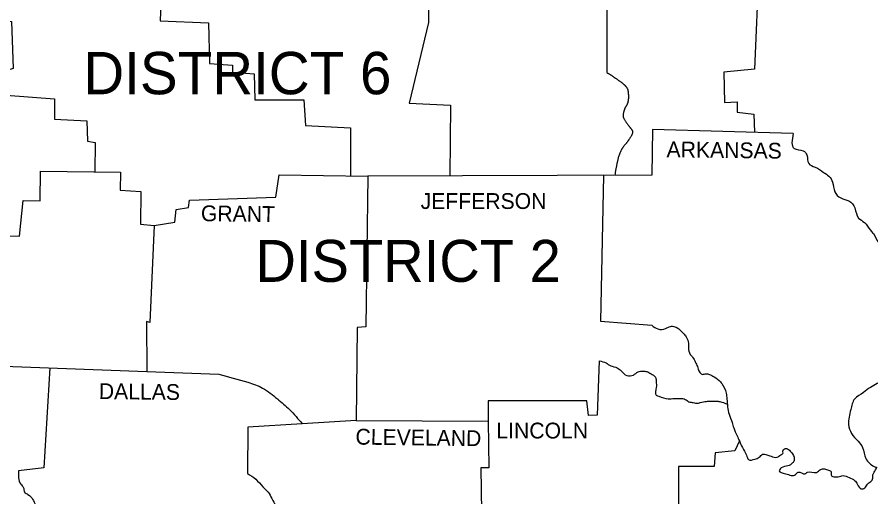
# Model space of a CAD drawing. Extents: x -0.3 to 2.65, y 0 to 1.9.
# Drawn here: x 1.1888 to 1.2937, y 0.6375 to 0.6965 of the extents above; entities that cross this region are included whole.
import ezdxf

# ---------------------------------------------------------------- set-up
doc = ezdxf.new("R2010")
doc.units = 0
doc.layers.add('Default', color=7, linetype='Continuous')

msp = doc.modelspace()

# ---------------------------------------------------------------- linework, layer by layer
at = {"layer": 'Default'}
for points in [[(1.25468, 0.71544), (1.25476, 0.70736), (1.26121, 0.70723), (1.26127, 0.68967)], [(1.23665, 0.7134), (1.2393, 0.71325), (1.23935, 0.69579), (1.23697, 0.68591), (1.24205, 0.68565), (1.24197, 0.67695)], [(1.27994, 0.70259), (1.27939, 0.69009), (1.27566, 0.6897), (1.27574, 0.68599), (1.27727, 0.68604), (1.27729, 0.68477), (1.27934, 0.68454), (1.27942, 0.68231)], [(1.2011, 0.70204), (1.20654, 0.70171), (1.20634, 0.696), (1.2123, 0.69577), (1.21243, 0.69079), (1.21523, 0.69056), (1.21523, 0.6897), (1.2179, 0.68949), (1.21798, 0.6863), (1.224, 0.6863), (1.22421, 0.68314), (1.22976, 0.68288), (1.22973, 0.67694)], [(1.18204, 0.69644), (1.18808, 0.69592), (1.18826, 0.69017), (1.18751, 0.68993), (1.18741, 0.68687), (1.19337, 0.68643), (1.19337, 0.68392), (1.19734, 0.68371), (1.19742, 0.68122), (1.19835, 0.68106), (1.19832, 0.67745)], [(1.28417, 0.68218), (1.26689, 0.68267), (1.26679, 0.67704), (1.23188, 0.67691)], [(1.16278, 0.66994), (1.18904, 0.66955), (1.18953, 0.67391), (1.19161, 0.67388), (1.19166, 0.67754), (1.20149, 0.67741), (1.20144, 0.6752), (1.20398, 0.67502), (1.20395, 0.67103), (1.20561, 0.67087)], [(1.20561, 0.67087), (1.20815, 0.67126), (1.20833, 0.67282), (1.20984, 0.67308), (1.20994, 0.67398), (1.22057, 0.67432), (1.22099, 0.67707), (1.23188, 0.67691)], [(1.26084, 0.67702), (1.26049, 0.6591), (1.26679, 0.6586)], [(1.23188, 0.67691), (1.23165, 0.6584), (1.23056, 0.65832), (1.23046, 0.64688)], [(1.20561, 0.67087), (1.20507, 0.65894), (1.20468, 0.65907), (1.2047, 0.65291)], [(1.15758, 0.65772), (1.15745, 0.66024), (1.1582, 0.66029), (1.15867, 0.6662), (1.16567, 0.66571), (1.16552, 0.66211), (1.17457, 0.66161), (1.17465, 0.65943), (1.18284, 0.65894), (1.18424, 0.65648), (1.18339, 0.65536), (1.1838, 0.65368), (1.2047, 0.65291)], [(1.26033, 0.65422), (1.26007, 0.64753), (1.25901, 0.6475), (1.2588, 0.64932), (1.24666, 0.64929), (1.24669, 0.6468)], [(1.19278, 0.65335), (1.19205, 0.64107), (1.18894, 0.64071)], [(1.2047, 0.65291), (1.21355, 0.65259)], [(1.23046, 0.64688), (1.22382, 0.64648)], [(1.23046, 0.64688), (1.24669, 0.6468)], [(1.24669, 0.6468), (1.24674, 0.64107), (1.24576, 0.64105), (1.24604, 0.62211)], [(1.22382, 0.64648), (1.21713, 0.64608), (1.21707, 0.64037)], [(1.27755, 0.64437), (1.27698, 0.64315), (1.27457, 0.64291), (1.27444, 0.64125), (1.27008, 0.64125), (1.27003, 0.62762)]]:
    msp.add_lwpolyline(points, dxfattribs=at)
msp.add_open_spline([(1.26127, 0.68967), (1.26136, 0.68961), (1.26146, 0.68955), (1.26156, 0.68948), (1.26165, 0.68942), (1.26175, 0.68936), (1.26184, 0.68929), (1.26203, 0.68916), (1.26222, 0.68903), (1.26241, 0.6889), (1.26251, 0.68883), (1.26261, 0.68876), (1.26271, 0.68869), (1.26281, 0.68863), (1.26291, 0.68856), (1.26301, 0.68849), (1.26311, 0.68842), (1.2632, 0.68834), (1.26329, 0.68826), (1.26334, 0.68822), (1.26339, 0.68818), (1.26344, 0.68813), (1.26346, 0.68811), (1.26348, 0.68809), (1.2635, 0.68806), (1.26353, 0.68804), (1.26355, 0.68801), (1.26357, 0.68799), (1.26365, 0.6879), (1.26371, 0.68781), (1.26376, 0.68771), (1.2638, 0.68761), (1.26384, 0.68751), (1.26386, 0.6874), (1.26387, 0.6873), (1.26389, 0.68719), (1.2639, 0.68708), (1.2639, 0.68703), (1.2639, 0.68698), (1.26391, 0.68693), (1.26391, 0.68687), (1.26391, 0.68682), (1.26391, 0.68677), (1.26391, 0.6867), (1.26391, 0.68663), (1.26391, 0.68655), (1.26391, 0.68648), (1.2639, 0.68641), (1.26389, 0.68634), (1.26389, 0.68627), (1.26387, 0.6862), (1.26386, 0.68612), (1.26385, 0.68605), (1.26383, 0.68598), (1.26381, 0.68591), (1.26379, 0.68585), (1.26376, 0.68578), (1.26373, 0.68572), (1.2637, 0.68566), (1.26366, 0.68561), (1.26363, 0.68555), (1.2636, 0.68549), (1.26356, 0.68543), (1.26353, 0.68537), (1.26349, 0.68531), (1.26347, 0.68525), (1.26344, 0.68519), (1.26343, 0.68514), (1.26341, 0.68509), (1.2634, 0.68505), (1.26338, 0.685), (1.26336, 0.68495), (1.26335, 0.6849), (1.26332, 0.6848), (1.2633, 0.6847), (1.26328, 0.6846), (1.26326, 0.6845), (1.26326, 0.6844), (1.26326, 0.6843), (1.26327, 0.68425), (1.26327, 0.6842), (1.26329, 0.68415), (1.2633, 0.68411), (1.26332, 0.68406), (1.26334, 0.68402), (1.26342, 0.68387), (1.26351, 0.68373), (1.2636, 0.6836), (1.26369, 0.68346), (1.26379, 0.68332), (1.26389, 0.68319), (1.26393, 0.68313), (1.26397, 0.68308), (1.26401, 0.68303), (1.26406, 0.68297), (1.2641, 0.68292), (1.26415, 0.68287), (1.26421, 0.68279), (1.26428, 0.68271), (1.26433, 0.68262), (1.26434, 0.68261), (1.26435, 0.6826), (1.26436, 0.68258), (1.26436, 0.68257), (1.26437, 0.68256), (1.26438, 0.68254), (1.26442, 0.68245), (1.26443, 0.68234), (1.26441, 0.68225), (1.26439, 0.68214), (1.26435, 0.68202), (1.26429, 0.68193), (1.26419, 0.68176), (1.26409, 0.6816), (1.26398, 0.68145), (1.26395, 0.6814), (1.26392, 0.68135), (1.26389, 0.6813), (1.26385, 0.68125), (1.26382, 0.68119), (1.26378, 0.68114), (1.26375, 0.68109), (1.26371, 0.68105), (1.26367, 0.681), (1.26359, 0.68091), (1.26351, 0.68081), (1.26344, 0.68072), (1.26336, 0.68063), (1.26329, 0.68053), (1.26321, 0.68044), (1.26318, 0.68039), (1.26315, 0.68034), (1.26312, 0.68029), (1.26308, 0.68024), (1.26306, 0.68018), (1.26303, 0.68013), (1.26293, 0.67993), (1.26284, 0.67973), (1.26277, 0.67952), (1.2627, 0.67931), (1.26264, 0.6791), (1.26259, 0.67888), (1.26255, 0.67873), (1.26252, 0.67858), (1.26249, 0.67842), (1.26246, 0.67827), (1.26243, 0.67811), (1.26239, 0.67796), (1.26236, 0.6778), (1.26234, 0.67765), (1.26231, 0.67749), (1.26228, 0.67734), (1.26226, 0.67718), (1.26223, 0.67703)], degree=3, dxfattribs=at)
for points in [[(1.28417, 0.68218), (1.2843, 0.68031), (1.2854, 0.68003), (1.28585, 0.67953), (1.28608, 0.67848), (1.28686, 0.67803), (1.28791, 0.67739), (1.28855, 0.67693), (1.289, 0.6762), (1.28928, 0.67501), (1.29001, 0.67424), (1.29101, 0.67387), (1.29174, 0.67301), (1.2922, 0.67177), (1.29293, 0.67123), (1.29366, 0.67027), (1.29402, 0.66986), (1.29466, 0.66876), (1.2953, 0.66821), (1.29576, 0.66789), (1.29649, 0.66767), (1.2974, 0.66707), (1.29799, 0.66616), (1.29799, 0.66547), (1.29777, 0.66443), (1.29758, 0.66333), (1.29749, 0.6621), (1.2974, 0.661), (1.29781, 0.66009), (1.29758, 0.65872), (1.29713, 0.65799), (1.29708, 0.65699), (1.29694, 0.65548), (1.29676, 0.65461), (1.29635, 0.6532), (1.2958, 0.65251)], [(1.28417, 0.68218), (1.2843, 0.68031), (1.2854, 0.68003), (1.28585, 0.67953), (1.28608, 0.67848), (1.28686, 0.67803), (1.28791, 0.67739), (1.28855, 0.67693), (1.289, 0.6762), (1.28928, 0.67501), (1.29001, 0.67424), (1.29101, 0.67387), (1.29174, 0.67301), (1.2922, 0.67177), (1.29293, 0.67123), (1.29366, 0.67027), (1.29402, 0.66986), (1.29466, 0.66876), (1.2953, 0.66821), (1.29576, 0.66789), (1.29649, 0.66767), (1.2974, 0.66707), (1.29799, 0.66616), (1.29799, 0.66547), (1.29777, 0.66443), (1.29758, 0.66333), (1.29749, 0.6621), (1.2974, 0.661), (1.29781, 0.66009), (1.29758, 0.65872), (1.29713, 0.65799), (1.29708, 0.65699), (1.29694, 0.65548), (1.29676, 0.65461), (1.29635, 0.6532), (1.29576, 0.65247)], [(1.26679, 0.6586), (1.26752, 0.65814), (1.26848, 0.65819), (1.26907, 0.65845), (1.26962, 0.65842), (1.27027, 0.65801), (1.27076, 0.65749), (1.27107, 0.65707), (1.27128, 0.6564), (1.27128, 0.65583), (1.27151, 0.655), (1.2718, 0.65466), (1.27213, 0.65409), (1.27239, 0.65352), (1.2725, 0.65318), (1.27301, 0.65256), (1.27348, 0.65264), (1.27387, 0.65256), (1.27444, 0.65225), (1.27524, 0.65163), (1.2754, 0.65142), (1.27592, 0.65025), (1.27602, 0.64953), (1.2761, 0.64857), (1.27628, 0.64766), (1.27667, 0.64665), (1.27685, 0.64597), (1.27727, 0.64501), (1.27755, 0.64437), (1.27792, 0.64356), (1.27843, 0.64263), (1.27869, 0.64208), (1.27947, 0.64214), (1.27999, 0.64237), (1.28041, 0.64273), (1.28092, 0.64268), (1.28144, 0.6425), (1.28219, 0.64237), (1.28264, 0.64265), (1.2829, 0.64284), (1.28292, 0.64323), (1.28334, 0.64346), (1.2838, 0.64312), (1.28427, 0.6424), (1.28427, 0.64195), (1.28409, 0.64167), (1.28352, 0.64131), (1.28269, 0.64105), (1.28245, 0.64071), (1.28323, 0.64035), (1.28445, 0.64024), (1.28479, 0.64055), (1.28562, 0.64032), (1.28593, 0.64053), (1.28702, 0.6405), (1.28754, 0.64087), (1.28852, 0.64079), (1.28883, 0.64058), (1.28883, 0.64019), (1.28969, 0.63998), (1.29029, 0.64011), (1.29104, 0.63988), (1.29171, 0.63952), (1.29208, 0.63902), (1.29254, 0.63848), (1.29296, 0.63861), (1.29329, 0.63905), (1.29397, 0.63978), (1.29397, 0.64022), (1.29412, 0.64053), (1.29443, 0.6411)], [(1.26033, 0.65422), (1.26116, 0.65396), (1.26173, 0.65362), (1.26254, 0.65337), (1.263, 0.653), (1.26373, 0.65241), (1.26453, 0.65248), (1.2651, 0.65287), (1.2657, 0.65295), (1.26617, 0.6529), (1.26669, 0.65264), (1.26723, 0.6522), (1.26733, 0.65163), (1.26733, 0.65095), (1.26733, 0.64999), (1.26765, 0.64986), (1.26879, 0.64955), (1.26956, 0.6496), (1.27027, 0.6496), (1.27089, 0.64948), (1.27135, 0.64919), (1.27174, 0.64911), (1.27229, 0.64901), (1.27275, 0.64909), (1.27351, 0.64924), (1.27397, 0.64927), (1.27473, 0.64927), (1.27514, 0.64922), (1.27607, 0.64889)], [(1.21355, 0.65259), (1.21713, 0.65158), (1.21894, 0.65088), (1.22076, 0.64955), (1.22226, 0.64823), (1.22382, 0.64648)], [(1.29576, 0.65247), (1.29448, 0.65142), (1.29366, 0.65096), (1.29279, 0.65032), (1.29174, 0.64955), (1.29124, 0.64822), (1.29097, 0.6464), (1.29133, 0.6453), (1.29215, 0.64434), (1.2927, 0.64357), (1.29311, 0.6422), (1.29411, 0.64124), (1.29443, 0.6411)], [(1.18894, 0.64071), (1.18894, 0.63985), (1.18922, 0.63905), (1.18953, 0.63869), (1.18969, 0.63806), (1.1901, 0.6378), (1.19067, 0.63723), (1.19101, 0.63648), (1.19122, 0.63596), (1.19124, 0.63532), (1.19127, 0.63469), (1.19137, 0.63394), (1.19192, 0.63254), (1.19207, 0.632), (1.19215, 0.63153), (1.1922, 0.63075), (1.19218, 0.62984), (1.19194, 0.62934)], [(1.21707, 0.64037), (1.21811, 0.63967), (1.21897, 0.63874), (1.21962, 0.63809), (1.22006, 0.63729), (1.22057, 0.63638), (1.22138, 0.63464), (1.22205, 0.63404), (1.22301, 0.63345), (1.22358, 0.63306), (1.22418, 0.63174), (1.22447, 0.63041), (1.22496, 0.62922), (1.22519, 0.62831), (1.22478, 0.62741), (1.22467, 0.62559), (1.22498, 0.62432), (1.22532, 0.62344), (1.22555, 0.62237), (1.2254, 0.62206)]]:
    msp.add_spline(points, degree=3, dxfattribs=at)

# ---------------------------------------------------------------- texts
for s, height, p in [('DISTRICT 6', 0.005203, (1.1969, 0.68699)), ('JEFFERSON', 0.001945, (1.23837, 0.67289)), ('DISTRICT 2', 0.005157, (1.21806, 0.66393)), ('LINCOLN', 0.001945, (1.24768, 0.64468))]:
    msp.add_text(s, height=height, dxfattribs=at).set_placement(p)
for s, rotation, p in [('ARKANSAS', 359.2655, (1.26859, 0.67925)), ('GRANT', 359.3139, (1.21135, 0.67139)), ('DALLAS', 359.2802, (1.1988, 0.64953)), ('CLEVELAND', 359.2412, (1.23035, 0.64393))]:
    msp.add_text(s, height=0.001945, rotation=rotation, dxfattribs=at).set_placement(p)

doc.saveas('drawing.dxf')
